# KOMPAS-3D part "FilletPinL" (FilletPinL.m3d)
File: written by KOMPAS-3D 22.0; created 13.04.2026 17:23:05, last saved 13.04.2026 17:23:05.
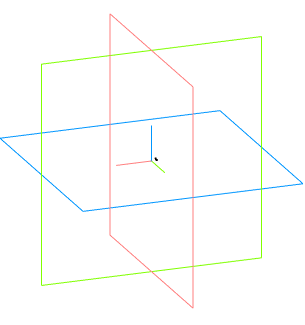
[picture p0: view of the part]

Document properties: Автор: Andrey; Полное имя файла: C:\Users\User1\Documents\FilletPinL.m3d

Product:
- Part/product: FilletPinL

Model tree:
1. Операция без истории:1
